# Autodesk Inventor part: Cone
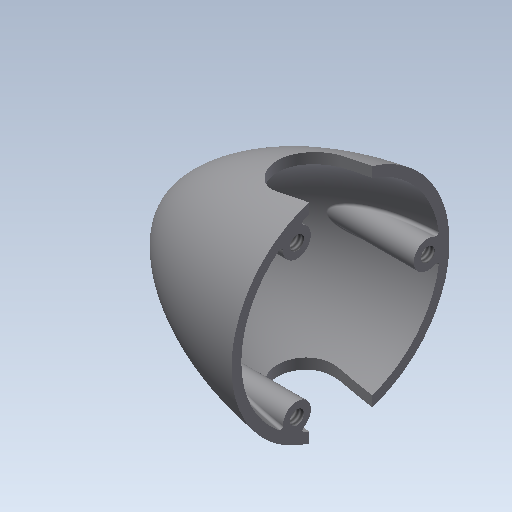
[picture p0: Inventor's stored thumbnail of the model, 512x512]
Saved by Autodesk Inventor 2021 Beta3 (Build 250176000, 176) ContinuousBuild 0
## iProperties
Created: 2013-05
Part Number: Cone
Material: Generic
Document SubType Name: Modeling
Designer: John
Density: 1 g/cm^3
Appearance: Default
Author: John
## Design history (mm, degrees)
sketch "Sketch1"
  geometry: L1 (0, 0)-(0, 28.575); L2 (0, 28.575)-(2.925, 28.059); L3 (44.45, 0)-(0, 0); L4 (44.45, 0)-(44.45, -6.273); L5 (2.925, 28.059)-(28.682, 23.518); L6 (28.682, 23.518)-(44.45, 9.587); L7 (44.45, 9.587)-(44.45, 0)
  constraints: 8 end point, 2 collinear, 2 perpendicular, 1 vertical, 3 other
  dimensions: "d0" = 44.45 distance of L3.start L1.start; "d1" = 10 deg angle of L3 L2; "d3" = 28.575 distance of L1.start L1.end
revolve "Revolution1" sketch "Sketch1" stored, may be unused: angle "d2" = 90 deg
sketch "Sketch2"
  geometry: L1 (2.925, -28.059)-(0, -28.575) reference; L2 (0, -28.575)-(0, 28.575) reference; L3 (0, 28.575)-(2.925, 28.059) reference; L4 (0, 8.255)-(8.255, 8.255); L5 (8.255, -8.255)-(0, -8.255); L6 (0, 0)-(8.255, 0); A1 r 8.255 centre (8.255, 0) between (8.255, -8.255) and (8.255, 8.255); 1 further point
  constraints: 6 end point, 2 perpendicular, 2 point on circle, 2 point on line, 2 tangent, 1 centre point, 1 horizontal, 2 other
  dimensions: "d4" = 8.255 radius of A1; "d5" = 8.255 distance of L4.start L4.end
extrude "Extrusion1" cut sketch "Sketch2" extent not by distance; stored distance "d6" = 25.4; taper "d7" = 0 deg
shell "Shell1" dims "d8" = 2.54
sketch "Sketch3"
  geometry: L1 (8.255, -24.65)-(8.255, -27.357); L2 (8.255, 27.357)-(8.255, 24.65); C1 r 2.381 at (-11.43, 19.797); C2 r 3.651 at (-11.43, 19.797); A1 r 25.996 centre (0, 0) between (-8.255, 24.65) and (-8.255, -24.65) reference; A2 r 25.996 centre (0, 0) between (8.255, -24.65) and (8.255, 24.65); A3 r 28.575 centre (0, 0) between (8.255, -27.357) and (8.255, 27.357)
  constraints: 4 centre point, 4 end point, 4 point on circle, 1 coincident
  dimensions: "d9" = 11.43 horizontal distance of A1.centre C2.centre; "d10" = 19.79734 vertical distance of A1.centre C1.centre; "d11" = 1.27 radial gap between concentric circles of C2 C1; "d12" = 4.7625 diameter of C1
extrude "Extrusion2" join sketch "Sketch3" stored distance "d13" = 0; taper "d14" = 0 deg
fillet "Fillet1" dims "d15" = 0.635
sketch "Sketch4"
  geometry: A1 r 3.651 centre (-11.43, 19.797) between (-15.08, 19.878) and (-9.675, 22.999) reference
hole "Hole1" sketch "Sketch4" at (-11.43, 19.797) diameter "d16" = 3.683; stored, may be unused: countersink angle "d20" = 82 deg, drill point angle "d22" = 118 deg; dims "d17" = 10.16, "d18" = 9.525, "d19" = 6.35, "d21" = 12.7
pattern_circular "Circular Pattern1" dims angle "d24" = 360 deg
body "Solid1"
node "Project Cut Edges1"
